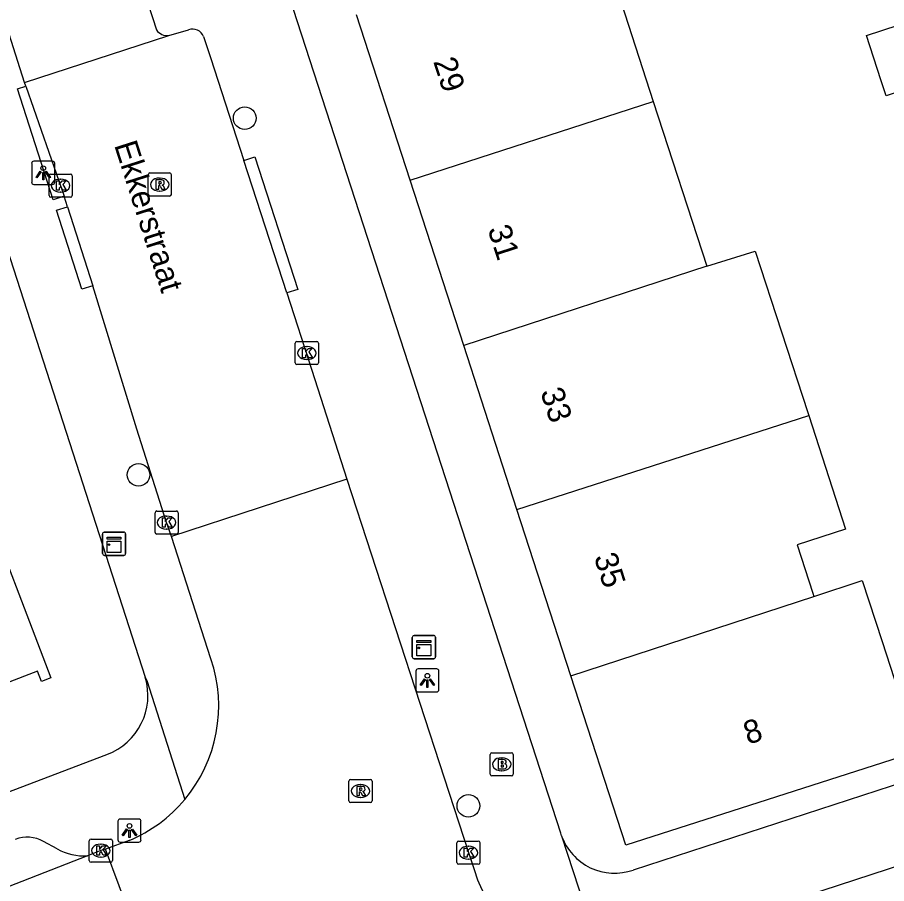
# Model space of a CAD drawing. Extents: x 159265 to 160143, y 383413 to 384319.
# Drawn here: x 159427.89 to 159465.42, y 383853.98 to 383891.39 of the extents above; entities that cross this region are included whole.
import ezdxf

# ---------------------------------------------------------------- set-up
doc = ezdxf.new("R2010")
doc.units = 0
for name, color, linetype in [('IMGEO_Boom', 7, 'Continuous'), ('IMGEO_Brandkraan', 7, 'Continuous'), ('IMGEO_Kast', 7, 'Continuous'), ('IMGEO_Kolk', 7, 'Continuous'), ('IMGEO_Lichtpunt', 7, 'Continuous'), ('IMGEO_Openbare_ruimte_label', 7, 'Continuous'), ('IMGEO_Pand', 7, 'Continuous'), ('IMGEO_Pand_nummerreeks', 7, 'Continuous'), ('IMGEO_Rijbaan_lokaal_gesloten', 7, 'Continuous'), ('IMGEO_Rijbaan_lokaal_open', 7, 'Continuous'), ('IMGEO_Rioolput', 7, 'Continuous'), ('IMGEO_Voetpad_open', 7, 'Continuous')]:
    doc.layers.add(name, color=color, linetype=linetype)

msp = doc.modelspace()

# ---------------------------------------------------------------- linework, layer by layer
at = {"layer": 'IMGEO_Boom'}
for centre in [(159437.707, 383887.037), (159433.125, 383871.635), (159447.364, 383857.337)]:
    msp.add_circle(centre, 0.489, dxfattribs=at)
at = {"layer": 'IMGEO_Brandkraan'}
for p, q in [((159448.38, 383859.634), (159449.232, 383859.634)), ((159448.305, 383858.708), (159448.305, 383859.56)), ((159448.793, 383859.414), (159448.818, 383859.414)), ((159449.306, 383859.56), (159449.306, 383858.708)), ((159448.816, 383858.854), (159448.791, 383858.854)), ((159449.232, 383858.634), (159448.38, 383858.634))]:
    msp.add_line(p, q, dxfattribs=at)
for points in [[(159448.38, 383859.634), (159449.232, 383859.634)], [(159448.305, 383858.708), (159448.305, 383859.56)], [(159448.653, 383859.334), (159448.653, 383858.934), (159448.866, 383858.934)], [(159448.884, 383859.334), (159448.653, 383859.334)], [(159448.832, 383859.253), (159448.778, 383859.253), (159448.778, 383859.177)], [(159449.306, 383859.56), (159449.306, 383858.708)], [(159448.778, 383859.177), (159448.831, 383859.177)], [(159448.84, 383859.101), (159448.778, 383859.101), (159448.778, 383859.02)], [(159448.778, 383859.02), (159448.84, 383859.02)], [(159449.232, 383858.634), (159448.38, 383858.634)]]:
    msp.add_lwpolyline(points, dxfattribs=at)
for centre, radius, start, end in [((159448.382, 383859.558), 0.0765, 91.552, 178.448), ((159448.382, 383859.558), 0.0765, 91.552, 178.448), ((159449.23, 383859.558), 0.0765, 1.552, 88.448), ((159449.23, 383859.558), 0.0765, 1.552, 88.448), ((159448.833, 383859.215), 0.0379, 267.8285, 90.9355), ((159448.888, 383859.189), 0.145, 59.4692, 91.5367), ((159448.913, 383859.236), 0.0922, 285.5137, 58.1501), ((159448.841, 383859.06), 0.0404, 269.8759, 90.5077), ((159448.872, 383859.185), 0.251, 268.6676, 293.5347), ((159448.918, 383859.044), 0.105, 301.3115, 78.989), ((159448.382, 383858.71), 0.0765, 181.552, 268.448), ((159448.382, 383858.71), 0.0765, 181.552, 268.448), ((159449.23, 383858.71), 0.0765, 271.552, 358.448), ((159449.23, 383858.71), 0.0765, 271.552, 358.448)]:
    msp.add_arc(centre, radius, start, end, dxfattribs=at)
for centre, major_axis, ratio, start_param, end_param in [((159448.792, 383859.134), (-0.387, 0.002), 0.722429, 4.712389, 7.853982), ((159448.817, 383859.134), (-0.39, 0.002), 0.717154, 1.570796, 4.712389)]:
    msp.add_ellipse(centre, major_axis=major_axis, ratio=ratio, start_param=start_param, end_param=end_param, dxfattribs=at)
at = {"layer": 'IMGEO_Kast'}
for p, q in [((159431.568, 383868.232), (159431.568, 383869.073)), ((159431.568, 383869.073), (159431.568, 383868.232)), ((159431.643, 383869.157), (159432.484, 383869.157)), ((159432.484, 383869.157), (159431.643, 383869.157)), ((159432.568, 383869.082), (159432.568, 383868.241)), ((159432.568, 383868.241), (159432.568, 383869.082)), ((159432.493, 383868.157), (159431.652, 383868.157)), ((159431.652, 383868.157), (159432.493, 383868.157)), ((159444.944, 383863.77), (159444.944, 383864.611)), ((159444.944, 383864.611), (159444.944, 383863.77)), ((159445.019, 383864.695), (159445.86, 383864.695)), ((159445.86, 383864.695), (159445.019, 383864.695)), ((159445.944, 383864.62), (159445.944, 383863.779)), ((159445.944, 383863.779), (159445.944, 383864.62)), ((159445.869, 383863.695), (159445.028, 383863.695)), ((159445.028, 383863.695), (159445.869, 383863.695))]:
    msp.add_line(p, q, dxfattribs=at)
for points in [[(159431.763, 383868.947), (159432.363, 383868.947), (159432.363, 383868.862), (159431.763, 383868.862), (159431.763, 383868.947)], [(159431.763, 383868.772), (159432.363, 383868.772), (159432.363, 383868.283), (159431.763, 383868.283), (159431.763, 383868.772)], [(159445.139, 383864.485), (159445.739, 383864.485), (159445.739, 383864.4), (159445.139, 383864.4), (159445.139, 383864.485)], [(159445.139, 383864.31), (159445.739, 383864.31), (159445.739, 383863.821), (159445.139, 383863.821), (159445.139, 383864.31)]]:
    msp.add_lwpolyline(points, dxfattribs=at)
for centre in [(159431.847, 383868.621), (159445.223, 383864.159)]:
    msp.add_circle(centre, 0.0377, dxfattribs=at)
for centre, start, end in [((159431.646, 383869.079), 92.4484, 184.2845), ((159431.646, 383869.079), 92.4484, 184.2845), ((159432.49, 383869.079), 2.4484, 94.2845), ((159432.49, 383869.079), 2.4484, 94.2845), ((159431.646, 383868.235), 182.4484, 274.2845), ((159431.646, 383868.235), 182.4484, 274.2845), ((159432.49, 383868.235), 272.4484, 4.2845), ((159432.49, 383868.235), 272.4484, 4.2845), ((159445.022, 383864.617), 92.4484, 184.2845), ((159445.022, 383864.617), 92.4484, 184.2845), ((159445.866, 383864.617), 2.4484, 94.2845), ((159445.866, 383864.617), 2.4484, 94.2845), ((159445.022, 383863.773), 182.4484, 274.2845), ((159445.022, 383863.773), 182.4484, 274.2845), ((159445.866, 383863.773), 272.4484, 4.2845), ((159445.866, 383863.773), 272.4484, 4.2845)]:
    msp.add_arc(centre, 0.0779, start, end, dxfattribs=at)
at = {"layer": 'IMGEO_Kolk'}
for p, q in [((159429.259, 383883.7), (159429.259, 383884.552)), ((159429.334, 383884.626), (159430.186, 383884.626)), ((159429.747, 383884.406), (159429.772, 383884.406)), ((159430.26, 383884.552), (159430.26, 383883.7)), ((159430.186, 383883.626), (159429.334, 383883.626)), ((159429.77, 383883.846), (159429.745, 383883.846)), ((159439.889, 383876.468), (159439.889, 383877.32)), ((159439.964, 383877.394), (159440.816, 383877.394)), ((159440.89, 383877.32), (159440.89, 383876.468)), ((159440.377, 383877.174), (159440.402, 383877.174)), ((159440.4, 383876.614), (159440.375, 383876.614)), ((159440.816, 383876.394), (159439.964, 383876.394)), ((159433.835, 383869.147), (159433.835, 383869.999)), ((159433.91, 383870.073), (159434.762, 383870.073)), ((159434.323, 383869.853), (159434.348, 383869.853)), ((159434.836, 383869.999), (159434.836, 383869.147)), ((159434.762, 383869.073), (159433.91, 383869.073)), ((159434.346, 383869.293), (159434.321, 383869.293)), ((159430.997, 383854.979), (159430.997, 383855.831)), ((159431.072, 383855.905), (159431.924, 383855.905)), ((159431.998, 383855.831), (159431.998, 383854.979)), ((159431.485, 383855.685), (159431.51, 383855.685)), ((159446.866, 383854.891), (159446.866, 383855.743)), ((159446.941, 383855.817), (159447.793, 383855.817)), ((159447.354, 383855.597), (159447.379, 383855.597)), ((159447.867, 383855.743), (159447.867, 383854.891)), ((159431.508, 383855.125), (159431.483, 383855.125)), ((159431.924, 383854.905), (159431.072, 383854.905)), ((159447.793, 383854.817), (159446.941, 383854.817)), ((159447.377, 383855.037), (159447.352, 383855.037))]:
    msp.add_line(p, q, dxfattribs=at)
for points in [[(159429.259, 383883.7), (159429.259, 383884.552)], [(159429.334, 383884.626), (159430.186, 383884.626)], [(159430.26, 383884.552), (159430.26, 383883.7)], [(159429.58, 383884.326), (159429.703, 383884.326), (159429.703, 383884.175), (159429.833, 383884.326), (159429.997, 383884.326), (159429.851, 383884.175), (159430.004, 383883.926), (159429.852, 383883.926), (159429.767, 383884.09), (159429.703, 383884.023), (159429.703, 383883.926), (159429.58, 383883.926), (159429.58, 383884.326)], [(159430.186, 383883.626), (159429.334, 383883.626)], [(159439.889, 383876.468), (159439.889, 383877.32)], [(159439.964, 383877.394), (159440.816, 383877.394)], [(159440.89, 383877.32), (159440.89, 383876.468)], [(159440.21, 383877.094), (159440.333, 383877.094), (159440.333, 383876.943), (159440.463, 383877.094), (159440.627, 383877.094), (159440.481, 383876.943), (159440.634, 383876.694), (159440.482, 383876.694), (159440.397, 383876.858), (159440.333, 383876.791), (159440.333, 383876.694), (159440.21, 383876.694), (159440.21, 383877.094)], [(159440.816, 383876.394), (159439.964, 383876.394)], [(159433.835, 383869.147), (159433.835, 383869.999)], [(159433.91, 383870.073), (159434.762, 383870.073)], [(159434.156, 383869.773), (159434.279, 383869.773), (159434.279, 383869.622), (159434.409, 383869.773), (159434.573, 383869.773), (159434.427, 383869.622), (159434.58, 383869.373), (159434.428, 383869.373), (159434.343, 383869.537), (159434.279, 383869.47), (159434.279, 383869.373), (159434.156, 383869.373), (159434.156, 383869.773)], [(159434.836, 383869.999), (159434.836, 383869.147)], [(159434.762, 383869.073), (159433.91, 383869.073)], [(159430.997, 383854.979), (159430.997, 383855.831)], [(159431.072, 383855.905), (159431.924, 383855.905)], [(159431.998, 383855.831), (159431.998, 383854.979)], [(159431.318, 383855.605), (159431.441, 383855.605), (159431.441, 383855.454), (159431.571, 383855.605), (159431.735, 383855.605), (159431.589, 383855.454), (159431.742, 383855.205), (159431.59, 383855.205), (159431.505, 383855.369), (159431.441, 383855.302), (159431.441, 383855.205), (159431.318, 383855.205), (159431.318, 383855.605)], [(159446.866, 383854.891), (159446.866, 383855.743)], [(159446.941, 383855.817), (159447.793, 383855.817)], [(159447.187, 383855.517), (159447.31, 383855.517), (159447.31, 383855.366), (159447.44, 383855.517), (159447.604, 383855.517), (159447.458, 383855.366), (159447.611, 383855.117), (159447.459, 383855.117), (159447.374, 383855.281), (159447.31, 383855.214), (159447.31, 383855.117), (159447.187, 383855.117), (159447.187, 383855.517)], [(159447.867, 383855.743), (159447.867, 383854.891)], [(159431.924, 383854.905), (159431.072, 383854.905)], [(159447.793, 383854.817), (159446.941, 383854.817)]]:
    msp.add_lwpolyline(points, dxfattribs=at)
for centre, start, end in [((159429.336, 383884.55), 91.552, 178.448), ((159429.336, 383884.55), 91.552, 178.448), ((159430.184, 383884.55), 1.552, 88.448), ((159430.184, 383884.55), 1.552, 88.448), ((159429.336, 383883.702), 181.552, 268.448), ((159429.336, 383883.702), 181.552, 268.448), ((159430.184, 383883.702), 271.552, 358.448), ((159430.184, 383883.702), 271.552, 358.448), ((159439.966, 383877.318), 91.552, 178.448), ((159439.966, 383877.318), 91.552, 178.448), ((159440.814, 383877.318), 1.552, 88.448), ((159440.814, 383877.318), 1.552, 88.448), ((159439.966, 383876.47), 181.552, 268.448), ((159439.966, 383876.47), 181.552, 268.448), ((159440.814, 383876.47), 271.552, 358.448), ((159440.814, 383876.47), 271.552, 358.448), ((159433.912, 383869.997), 91.552, 178.448), ((159433.912, 383869.997), 91.552, 178.448), ((159434.76, 383869.997), 1.552, 88.448), ((159434.76, 383869.997), 1.552, 88.448), ((159433.912, 383869.149), 181.552, 268.448), ((159433.912, 383869.149), 181.552, 268.448), ((159434.76, 383869.149), 271.552, 358.448), ((159434.76, 383869.149), 271.552, 358.448), ((159431.074, 383855.829), 91.552, 178.448), ((159431.074, 383855.829), 91.552, 178.448), ((159431.922, 383855.829), 1.552, 88.448), ((159431.922, 383855.829), 1.552, 88.448), ((159446.943, 383855.741), 91.552, 178.448), ((159446.943, 383855.741), 91.552, 178.448), ((159447.791, 383855.741), 1.552, 88.448), ((159447.791, 383855.741), 1.552, 88.448), ((159431.074, 383854.981), 181.552, 268.448), ((159431.074, 383854.981), 181.552, 268.448), ((159431.922, 383854.981), 271.552, 358.448), ((159431.922, 383854.981), 271.552, 358.448), ((159446.943, 383854.893), 181.552, 268.448), ((159446.943, 383854.893), 181.552, 268.448), ((159447.791, 383854.893), 271.552, 358.448), ((159447.791, 383854.893), 271.552, 358.448)]:
    msp.add_arc(centre, 0.0765, start, end, dxfattribs=at)
for centre, major_axis, ratio, start_param, end_param in [((159429.746, 383884.126), (-0.387, 0.002), 0.722429, 4.712389, 7.853982), ((159429.771, 383884.126), (-0.39, 0.002), 0.717154, 1.570796, 4.712389), ((159440.376, 383876.894), (-0.387, 0.002), 0.722429, 4.712389, 7.853982), ((159440.401, 383876.894), (-0.39, 0.002), 0.717154, 1.570796, 4.712389), ((159434.322, 383869.573), (-0.387, 0.002), 0.722429, 4.712389, 7.853982), ((159434.347, 383869.573), (-0.39, 0.002), 0.717154, 1.570796, 4.712389), ((159431.484, 383855.405), (-0.387, 0.002), 0.722429, 4.712389, 7.853982), ((159431.509, 383855.405), (-0.39, 0.002), 0.717154, 1.570796, 4.712389), ((159447.353, 383855.317), (-0.387, 0.002), 0.722429, 4.712389, 7.853982), ((159447.378, 383855.317), (-0.39, 0.002), 0.717154, 1.570796, 4.712389)]:
    msp.add_ellipse(centre, major_axis=major_axis, ratio=ratio, start_param=start_param, end_param=end_param, dxfattribs=at)
at = {"layer": 'IMGEO_Lichtpunt'}
for p, q in [((159429.412, 383885.177), (159428.604, 383885.177)), ((159429.412, 383885.177), (159428.604, 383885.177)), ((159428.51, 383885.082), (159428.51, 383884.275)), ((159428.51, 383885.082), (159428.51, 383884.275)), ((159429.506, 383884.275), (159429.506, 383885.082)), ((159429.506, 383884.275), (159429.506, 383885.082)), ((159428.604, 383884.181), (159429.412, 383884.181)), ((159428.604, 383884.181), (159429.412, 383884.181)), ((159445.098, 383863.161), (159445.098, 383862.354)), ((159445.098, 383863.161), (159445.098, 383862.354)), ((159446, 383863.256), (159445.192, 383863.256)), ((159446, 383863.256), (159445.192, 383863.256)), ((159446.094, 383862.354), (159446.094, 383863.161)), ((159446.094, 383862.354), (159446.094, 383863.161)), ((159445.192, 383862.26), (159446, 383862.26)), ((159445.192, 383862.26), (159446, 383862.26)), ((159432.234, 383856.675), (159432.234, 383855.868)), ((159432.234, 383856.675), (159432.234, 383855.868)), ((159433.136, 383856.77), (159432.328, 383856.77)), ((159433.136, 383856.77), (159432.328, 383856.77)), ((159433.23, 383855.868), (159433.23, 383856.675)), ((159433.23, 383855.868), (159433.23, 383856.675)), ((159432.328, 383855.774), (159433.136, 383855.774)), ((159432.328, 383855.774), (159433.136, 383855.774))]:
    msp.add_line(p, q, dxfattribs=at)
for points in [[(159428.884, 383884.746), (159428.923, 383884.718), (159428.735, 383884.456), (159428.697, 383884.483), (159428.884, 383884.746)], [(159429.096, 383884.718), (159429.134, 383884.745), (159429.321, 383884.483), (159429.282, 383884.455), (159429.096, 383884.718)], [(159428.986, 383884.698), (159429.033, 383884.698), (159429.033, 383884.376), (159428.986, 383884.376), (159428.986, 383884.698)], [(159445.472, 383862.825), (159445.511, 383862.797), (159445.323, 383862.535), (159445.285, 383862.562), (159445.472, 383862.825)], [(159445.574, 383862.777), (159445.621, 383862.777), (159445.621, 383862.455), (159445.574, 383862.455), (159445.574, 383862.777)], [(159445.684, 383862.797), (159445.722, 383862.824), (159445.909, 383862.562), (159445.87, 383862.534), (159445.684, 383862.797)], [(159432.608, 383856.339), (159432.647, 383856.311), (159432.459, 383856.049), (159432.421, 383856.076), (159432.608, 383856.339)], [(159432.71, 383856.291), (159432.757, 383856.291), (159432.757, 383855.969), (159432.71, 383855.969), (159432.71, 383856.291)], [(159432.82, 383856.311), (159432.858, 383856.338), (159433.045, 383856.076), (159433.006, 383856.048), (159432.82, 383856.311)]]:
    msp.add_lwpolyline(points, dxfattribs=at)
for centre in [(159429.009, 383884.88), (159445.597, 383862.959), (159432.733, 383856.473)]:
    msp.add_circle(centre, 0.0994, dxfattribs=at)
for centre, start, end in [((159428.604, 383885.082), 90, 180), ((159428.604, 383885.082), 90, 180), ((159429.412, 383885.082), 0, 90), ((159429.412, 383885.082), 0, 90), ((159428.604, 383884.275), 180, 270), ((159428.604, 383884.275), 180, 270), ((159429.412, 383884.275), 270, 0), ((159429.412, 383884.275), 270, 360), ((159445.192, 383863.161), 90, 180), ((159445.192, 383863.161), 90, 180), ((159446, 383863.161), 0, 90), ((159446, 383863.161), 0, 90), ((159445.192, 383862.354), 180, 270), ((159445.192, 383862.354), 180, 270), ((159446, 383862.354), 270, 0), ((159446, 383862.354), 270, 360), ((159432.328, 383856.675), 90, 180), ((159432.328, 383856.675), 90, 180), ((159433.136, 383856.675), 0, 90), ((159433.136, 383856.675), 0, 90), ((159432.328, 383855.868), 180, 270), ((159432.328, 383855.868), 180, 270), ((159433.136, 383855.868), 270, 0), ((159433.136, 383855.868), 270, 360)]:
    msp.add_arc(centre, 0.0946, start, end, dxfattribs=at)
at = {"layer": 'IMGEO_Pand'}
for points in [[(159453.035, 383894.898), (159455.349, 383887.764)], [(159444.854, 383884.362), (159442.542, 383891.496)], [(159465.178, 383888.7), (159464.551, 383890.607), (159466.622, 383891.288), (159467.475, 383888.691), (159465.405, 383888.01), (159465.178, 383888.7)], [(159444.854, 383884.362), (159455.349, 383887.764)], [(159455.349, 383887.764), (159457.661, 383880.64)], [(159447.166, 383877.227), (159444.854, 383884.362)], [(159457.661, 383880.64), (159459.752, 383881.302), (159462.018, 383874.333), (159462.061, 383874.2)], [(159457.661, 383880.64), (159447.166, 383877.227)], [(159449.463, 383870.136), (159447.166, 383877.227)], [(159449.463, 383870.136), (159462.061, 383874.2)], [(159462.061, 383874.2), (159463.652, 383869.294), (159461.56, 383868.614), (159462.238, 383866.523), (159462.283, 383866.385)], [(159420.353, 383868.553), (159421.277, 383868.908), (159423.238, 383869.661), (159422.439, 383871.755), (159424.606, 383872.587), (159425.406, 383870.494), (159425.944, 383870.701), (159425.797, 383871.087), (159426.149, 383871.221), (159429.341, 383862.867), (159428.935, 383862.712), (159428.766, 383863.153), (159423.405, 383861.104), (159423.581, 383860.644), (159423.398, 383860.574)], [(159451.79, 383862.957), (159449.463, 383870.136)], [(159462.283, 383866.385), (159464.372, 383867.068), (159465.226, 383864.436), (159466.768, 383859.679), (159454.162, 383855.636), (159451.79, 383862.957)], [(159451.79, 383862.957), (159462.283, 383866.385)]]:
    msp.add_lwpolyline(points, dxfattribs=at)
at = {"layer": 'IMGEO_Rijbaan_lokaal_gesloten'}
for points in [[(159434.439, 383890.605), (159435.282, 383890.861)], [(159428.205, 383888.576), (159434.439, 383890.605)], [(159435.934, 383890.56), (159436.231, 383889.666), (159437.664, 383885.207)], [(159428.257, 383888.427), (159428.205, 383888.576)], [(159428.257, 383888.427), (159429.908, 383883.667)], [(159439.532, 383879.49), (159437.664, 383885.207)], [(159430.052, 383883.216), (159429.908, 383883.667)], [(159430.052, 383883.216), (159431.145, 383879.803)], [(159434.544, 383868.974), (159434.337, 383869.573), (159433.052, 383873.612), (159431.145, 383879.803)], [(159439.532, 383879.49), (159440.61, 383876.155), (159442.124, 383871.452)]]:
    msp.add_lwpolyline(points, dxfattribs=at)
msp.add_arc((159435.445, 383890.358), 0.529, 22.4818, 107.9568, dxfattribs=at)
at = {"layer": 'IMGEO_Rijbaan_lokaal_open'}
for points in [[(159428.205, 383888.576), (159424.574, 383899.985)], [(159431.521, 383898.176), (159433.895, 383890.849)], [(159442.124, 383871.452), (159434.544, 383868.974)], [(159442.124, 383871.452), (159447.368, 383855.317), (159447.613, 383854.588)], [(159436.248, 383863.684), (159434.544, 383868.974)], [(159455.114, 383851.251), (159455.32, 383851.315), (159461.274, 383853.231), (159490.804, 383862.881), (159492.458, 383863.406), (159493.091, 383863.631)], [(159432.721, 383855.842), (159431.695, 383855.47)], [(159431.695, 383855.47), (159431.498, 383855.404), (159431.28, 383855.319), (159430.92, 383855.178)], [(159433.465, 383850.712), (159431.695, 383855.47)], [(159430.92, 383855.178), (159411.861, 383847.734), (159383.623, 383837.11), (159371.844, 383832.486)]]:
    msp.add_lwpolyline(points, dxfattribs=at)
for centre, radius, start, end in [((159434.382, 383891.206), 0.603, 216.2326, 275.4521), ((159430.292, 383861.649), 6.294, 320.0764, 18.8643), ((159430.291, 383861.649), 6.295, 292.7114, 320.0899), ((159452.744, 383856.094), 5.347, 196.3547, 273.9065)]:
    msp.add_arc(centre, radius, start, end, dxfattribs=at)
at = {"layer": 'IMGEO_Rioolput'}
for p, q in [((159433.539, 383883.745), (159433.539, 383884.597)), ((159433.614, 383884.671), (159434.466, 383884.671)), ((159434.027, 383884.451), (159434.052, 383884.451)), ((159434.54, 383884.597), (159434.54, 383883.745)), ((159434.466, 383883.671), (159433.614, 383883.671)), ((159434.05, 383883.891), (159434.025, 383883.891)), ((159442.282, 383858.481), (159443.134, 383858.481)), ((159442.207, 383857.555), (159442.207, 383858.407)), ((159442.695, 383858.261), (159442.72, 383858.261)), ((159443.208, 383858.407), (159443.208, 383857.555)), ((159442.718, 383857.701), (159442.693, 383857.701)), ((159443.134, 383857.481), (159442.282, 383857.481))]:
    msp.add_line(p, q, dxfattribs=at)
for points in [[(159433.539, 383883.745), (159433.539, 383884.597)], [(159433.614, 383884.671), (159434.466, 383884.671)], [(159434.128, 383884.369), (159433.876, 383884.371), (159433.876, 383883.971)], [(159434.54, 383884.597), (159434.54, 383883.745)], [(159433.876, 383883.971), (159434, 383883.971), (159434, 383884.133), (159434.011, 383884.133)], [(159434.054, 383884.29), (159434, 383884.29), (159434, 383884.209)], [(159434, 383884.209), (159434.052, 383884.209)], [(159434.058, 383884.104), (159434.129, 383883.971), (159434.269, 383883.971), (159434.204, 383884.097)], [(159434.466, 383883.671), (159433.614, 383883.671)], [(159442.282, 383858.481), (159443.134, 383858.481)], [(159442.207, 383857.555), (159442.207, 383858.407)], [(159442.796, 383858.179), (159442.544, 383858.181), (159442.544, 383857.781)], [(159442.722, 383858.1), (159442.668, 383858.1), (159442.668, 383858.019)], [(159443.208, 383858.407), (159443.208, 383857.555)], [(159442.544, 383857.781), (159442.668, 383857.781), (159442.668, 383857.943), (159442.679, 383857.943)], [(159442.668, 383858.019), (159442.72, 383858.019)], [(159442.726, 383857.914), (159442.797, 383857.781), (159442.937, 383857.781), (159442.872, 383857.907)], [(159443.134, 383857.481), (159442.282, 383857.481)]]:
    msp.add_lwpolyline(points, dxfattribs=at)
for centre, radius, start, end in [((159433.616, 383884.595), 0.0765, 91.552, 178.448), ((159433.616, 383884.595), 0.0765, 91.552, 178.448), ((159434.127, 383884.259), 0.109, 350.3612, 89.416), ((159434.464, 383884.595), 0.0765, 1.552, 88.448), ((159434.464, 383884.595), 0.0765, 1.552, 88.448), ((159434.01, 383884.08), 0.0533, 26.0293, 88.6989), ((159434.036, 383884.398), 0.19, 274.7715, 282.9687), ((159434.06, 383884.194), 0.0964, 77.0061, 93.1865), ((159434.074, 383884.251), 0.0378, 276.6634, 79.6772), ((159434.125, 383884.259), 0.112, 277.5842, 350.9817), ((159434.109, 383884.044), 0.108, 29.5134, 73.7905), ((159433.616, 383883.747), 0.0765, 181.552, 268.448), ((159433.616, 383883.747), 0.0765, 181.552, 268.448), ((159434.464, 383883.747), 0.0765, 271.552, 358.448), ((159434.464, 383883.747), 0.0765, 271.552, 358.448), ((159442.284, 383858.405), 0.0765, 91.552, 178.448), ((159442.284, 383858.405), 0.0765, 91.552, 178.448), ((159443.132, 383858.405), 0.0765, 1.552, 88.448), ((159443.132, 383858.405), 0.0765, 1.552, 88.448), ((159442.728, 383858.004), 0.0964, 77.0061, 93.1865), ((159442.742, 383858.061), 0.0378, 276.6634, 79.6772), ((159442.795, 383858.069), 0.109, 350.3612, 89.416), ((159442.678, 383857.89), 0.0533, 26.0293, 88.6989), ((159442.704, 383858.208), 0.19, 274.7715, 282.9687), ((159442.793, 383858.069), 0.112, 277.5842, 350.9817), ((159442.777, 383857.854), 0.108, 29.5134, 73.7905), ((159442.284, 383857.557), 0.0765, 181.552, 268.448), ((159442.284, 383857.557), 0.0765, 181.552, 268.448), ((159443.132, 383857.557), 0.0765, 271.552, 358.448), ((159443.132, 383857.557), 0.0765, 271.552, 358.448)]:
    msp.add_arc(centre, radius, start, end, dxfattribs=at)
for centre, major_axis, ratio, start_param, end_param in [((159434.026, 383884.171), (-0.387, 0.002), 0.722429, 4.712389, 7.853982), ((159434.051, 383884.171), (-0.39, 0.002), 0.717154, 1.570796, 4.712389), ((159442.694, 383857.981), (-0.387, 0.002), 0.722429, 4.712389, 7.853982), ((159442.719, 383857.981), (-0.39, 0.002), 0.717154, 1.570796, 4.712389)]:
    msp.add_ellipse(centre, major_axis=major_axis, ratio=ratio, start_param=start_param, end_param=end_param, dxfattribs=at)
at = {"layer": 'IMGEO_Voetpad_open'}
for points in [[(159451.393, 383856.048), (159451.355, 383856.164), (159433.598, 383910.902)], [(159429.908, 383883.667), (159429.432, 383883.515), (159427.896, 383888.312), (159428.257, 383888.427)], [(159437.664, 383885.207), (159438.139, 383885.362), (159440.007, 383879.645), (159439.532, 383879.49)], [(159431.145, 383879.803), (159430.67, 383879.65), (159429.578, 383883.063), (159430.052, 383883.216)], [(159427.008, 383882.725), (159433.414, 383862.892)], [(159433.414, 383862.892), (159433.479, 383862.754), (159435.119, 383857.61)], [(159476.351, 383861.69), (159466.86, 383858.596), (159454.482, 383854.568)], [(159370.416, 383836.226), (159382.457, 383840.783), (159431.75, 383859.554)], [(159451.393, 383856.048), (159453.108, 383850.759)], [(159429.612, 383855.479), (159429.019, 383855.805)]]:
    msp.add_lwpolyline(points, dxfattribs=at)
for centre, radius, start, end in [((159430.812, 383862.105), 2.718, 290.1854, 16.8219), ((159428.32, 383854.533), 1.452, 61.2103, 110.8929), ((159453.675, 383856.847), 2.418, 199.3001, 289.4999), ((159430.793, 383857.62), 2.446, 241.1138, 272.9674)]:
    msp.add_arc(centre, radius, start, end, dxfattribs=at)

# ---------------------------------------------------------------- texts
at = {"layer": 'IMGEO_Openbare_ruimte_label'}
msp.add_text('Ekkerstraat', height=1, rotation=287.7643, dxfattribs=at).set_placement((159432.064, 383885.881))
at = {"layer": 'IMGEO_Pand_nummerreeks'}
for s, rotation, p in [('29', 287.9547, (159445.84, 383889.492)), ('31', 287.9547, (159448.187, 383882.249)), ('33', 287.9547, (159450.464, 383875.222)), ('35', 287.9563, (159452.776, 383868.088)), ('8', 17.7846, (159459.437, 383859.975))]:
    msp.add_text(s, height=1, rotation=rotation, dxfattribs=at).set_placement(p)

doc.saveas('drawing.dxf')
